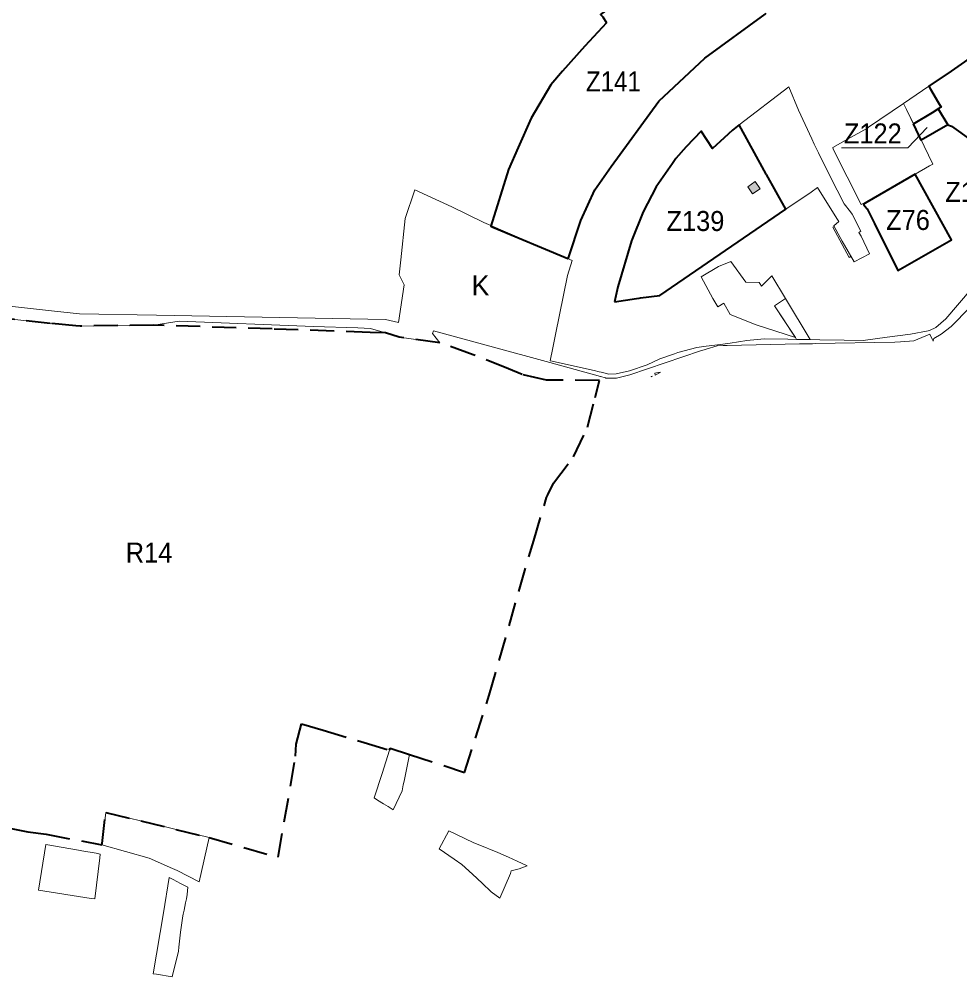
# Model space of a CAD drawing. Extents: x -650276 to -642489, y -1074425 to -1066658.
# Drawn here: x -647851 to -646722, y -1073778 to -1072629 of the extents above; entities that cross this region are included whole.
import ezdxf

# ---------------------------------------------------------------- set-up
doc = ezdxf.new("R2010")
doc.units = 0
doc.header["$LTSCALE"] = 9.6
doc.linetypes.add('MEDIUM_DASHED', pattern=[4.5, 3, -1.5])
for name, color, linetype, lineweight in [('1', 7, 'Continuous', 13), ('4', 7, 'Continuous', 40), ('43', 7, 'Continuous', 13), ('45', 7, 'Continuous', 40), ('46', 7, 'Continuous', 13), ('47', 7, 'Continuous', 13), ('61', 7, 'MEDIUM_DASHED', 40), ('62', 7, 'Continuous', 35)]:
    doc.layers.add(name, color=color, linetype=linetype, lineweight=lineweight)

msp = doc.modelspace()

# ---------------------------------------------------------------- hatches: boundary and pattern name
at = {"layer": '1'}
msp.add_hatch(color=256, dxfattribs=at).paths.add_polyline_path([(-646971.04, -1072838.99), (-646961.93, -1072832.83), (-646967.71, -1072824.33), (-646976.8, -1072830.5)])

# ---------------------------------------------------------------- linework, layer by layer
for p, q in [((-646855.3, -1072915.24), (-646853.054, -1072914.012)), ((-646920.755, -1073009.568), (-646919.54, -1073011.41)), ((-647087.96, -1073056.29), (-647081.63, -1073053.13)), ((-647092.58, -1073058.59), (-647090.83, -1073057.72)), ((-647424.76, -1073563.32), (-647420.98, -1073566.16))]:
    msp.add_line(p, q, dxfattribs=at)
for points in [[(-646849.28, -1072920.67), (-646830.67, -1072911.13), (-646840.69, -1072889.58), (-646843.77, -1072885.18), (-646841.08, -1072883.58), (-646851.49, -1072863.39), (-646853.76, -1072860.47), (-646861.08, -1072851.02), (-646877.79, -1072818.08), (-646892.15, -1072789.78), (-646897.03, -1072779.37), (-646900.09, -1072772.84), (-646916.01, -1072738.71), (-646927.67, -1072710.45), (-646987.154, -1072756.377), (-646954.51, -1072815.63)], [(-646778.198, -1072755.189), (-646755.1, -1072741.28), (-646744.94, -1072734.88), (-646747.87, -1072729.85), (-646757.5, -1072713.3), (-646759.55, -1072709.919), (-646789.83, -1072730.68)], [(-646789.83, -1072730.68), (-646786.56, -1072737.88), (-646778.198, -1072755.189)], [(-646954.51, -1072815.63), (-646931.1, -1072857.55), (-646900.9, -1072836.91), (-646893, -1072831.51), (-646869.88, -1072868.45), (-646867.436, -1072872.174), (-646873.71, -1072877.54), (-646863.45, -1072895.67), (-646849.28, -1072920.67)], [(-646873.3, -1072878.27), (-646874.85, -1072879.05), (-646855.3, -1072915.24)], [(-646853.054, -1072914.012), (-646863.45, -1072895.67), (-646873.298, -1072878.269)], [(-646997.71, -1072983.89), (-646966.57, -1072996.25), (-646919.54, -1073011.41), (-646944.76, -1072973.16), (-646931.62, -1072964.64), (-646947.88, -1072937.51), (-646960.29, -1072949.77), (-646962.41, -1072946.46), (-646963.13, -1072945.34), (-646979.1, -1072945.1), (-646997.15, -1072920.28), (-647011.86, -1072926.17), (-647032.61, -1072938.39), (-647018.82, -1072964.39)], [(-647018.82, -1072964.39), (-647012.79, -1072974.53), (-647005.6, -1072970.29), (-646997.71, -1072983.89)], [(-646931.62, -1072964.64), (-646944.76, -1072973.16), (-646920.755, -1073009.568)], [(-646919.54, -1073011.41), (-646918.156, -1073013.511), (-646902.136, -1073013.834), (-646931.62, -1072964.64)], [(-647081.63, -1073053.13), (-647081.66, -1073052.93), (-647088.34, -1073053.92), (-647087.96, -1073056.29)], [(-647090.83, -1073057.72), (-647092.67, -1073058), (-647092.58, -1073058.59)], [(-647420.98, -1073566.16), (-647413.53, -1073570.45), (-647407.81, -1073573.75), (-647401.88, -1073577.81), (-647391.32, -1073555.19), (-647389.85, -1073547.9), (-647388.91, -1073543.24), (-647382.45, -1073511.28), (-647405.5, -1073503.75), (-647406.33, -1073506.42), (-647415.01, -1073534.27), (-647424.76, -1073563.32)], [(-647661.19, -1073650.75), (-647634.63, -1073664.23), (-647622.63, -1073611.03), (-647686.73, -1073595.49), (-647746.63, -1073580.97), (-647751.31, -1073619.66), (-647694.7, -1073635.83)], [(-647250.75, -1073648.68), (-647241.27, -1073644.97), (-647253.11, -1073639.5), (-647263.52, -1073634.7), (-647276.6, -1073628.9), (-647300.1, -1073619.24), (-647303.33, -1073618.39), (-647306.03, -1073617.09), (-647335.29, -1073602.93), (-647346.74, -1073624.52), (-647328.83, -1073636.9), (-647319.58, -1073643.3)], [(-647753.78, -1073635.28), (-647753.27, -1073631.18), (-647758.16, -1073629.74), (-647775.27, -1073626.98), (-647779.3, -1073626.21), (-647818.46, -1073619.22), (-647827.23, -1073674.17)], [(-647827.23, -1073674.17), (-647764.01, -1073684.03), (-647759.96, -1073684.66), (-647753.78, -1073635.28)], [(-647694.7, -1073635.83), (-647666.8, -1073648.24), (-647661.19, -1073650.75)], [(-647319.58, -1073643.3), (-647306.74, -1073655.12), (-647295.17, -1073665.69), (-647284.57, -1073676.21), (-647274.16, -1073683.6), (-647261.22, -1073654.35), (-647260.32, -1073650.85), (-647250.75, -1073648.68)], [(-647670.44, -1073659.02), (-647677.6, -1073701.18), (-647689.67, -1073774.49)], [(-647648.15, -1073670.69), (-647652.31, -1073668.51), (-647656.92, -1073666.1), (-647665.93, -1073661.38), (-647670.44, -1073659.02)], [(-647689.67, -1073774.49), (-647685.72, -1073775.12), (-647666.96, -1073778.14), (-647659.58, -1073747.37), (-647659.07, -1073742.58), (-647657.12, -1073724.42), (-647654.08, -1073705.05), (-647653.73, -1073703.07), (-647652.75, -1073698.15), (-647650.96, -1073689.17), (-647650.01, -1073684.42), (-647649.01, -1073679.36), (-647648.15, -1073670.69)]]:
    msp.add_lwpolyline(points, dxfattribs=at)
for points in [[(-646857.61, -1072818.4), (-646840.87, -1072851.94), (-646838.22, -1072850.53), (-646837.81, -1072851.3), (-646775.85, -1072815.39), (-646758.9, -1072805.56), (-646754.96, -1072803.29), (-646786.56, -1072737.88), (-646789.83, -1072730.68), (-646831.91, -1072759.13), (-646833.27, -1072760.04), (-646857.03, -1072773.34), (-646874.79, -1072783.28), (-646874.23, -1072785.2)], [(-646971.04, -1072838.99), (-646961.93, -1072832.83), (-646967.71, -1072824.33), (-646976.8, -1072830.5)]]:
    msp.add_lwpolyline(points, close=True, dxfattribs=at)
at = {"layer": '4'}
for points in [[(-646987.154, -1072756.377), (-646995.02, -1072762.45), (-647005.249, -1072771.938), (-647019.06, -1072784.57), (-647032.7, -1072763.68), (-647050.492, -1072782.771)], [(-646954.7, -1072815.232), (-646957.105, -1072810.92), (-646987.154, -1072756.377)], [(-647050.492, -1072782.771), (-647063.04, -1072796.74), (-647067.22, -1072802.77), (-647086.65, -1072830.76), (-647102.38, -1072860.7), (-647116.33, -1072895.3)], [(-647136.39, -1072968.63), (-647110.32, -1072964.56), (-647107.01, -1072964.04), (-647105.4, -1072963.84), (-647082.36, -1072960.95), (-646931.1, -1072857.55), (-646954.51, -1072815.63), (-646954.7, -1072815.232)], [(-647116.33, -1072895.3), (-647132.47, -1072950.4), (-647136.39, -1072968.63)]]:
    msp.add_lwpolyline(points, dxfattribs=at)
at = {"layer": '45'}
for points in [[(-646993.05, -1072505.68), (-646994.2, -1072506.52), (-647153.2, -1072623.68), (-647150.75, -1072626.84), (-647146.21, -1072634.02)], [(-647192.069, -1072916.856), (-647177.144, -1072871.095), (-647160.08, -1072833.974), (-647140.764, -1072806.081), (-647083.498, -1072727.769), (-647028.234, -1072676.101), (-646956.061, -1072623.348), (-646954.617, -1072622.388)], [(-647146.21, -1072634.02), (-647172.36, -1072661.69), (-647198.77, -1072691.71), (-647212.92, -1072708.05)], [(-646737.05, -1072756.4), (-646732.5, -1072757.63), (-646708.65, -1072775.02), (-646702.45, -1072773.39), (-646712.46, -1072766.76), (-646711.79, -1072750.02), (-646677.39, -1072724.85), (-646660.89, -1072709.97), (-646643.36, -1072746.04), (-646647.93, -1072759.01), (-646612.11, -1072774.56), (-646581.92, -1072723.91), (-646589.37, -1072709.83), (-646605.23, -1072679.37), (-646627.32, -1072636.95), (-646629.86, -1072632.07), (-646648.27, -1072647.48), (-646669.6, -1072654.53), (-646697.89, -1072667.65)], [(-646697.89, -1072667.65), (-646732.95, -1072691.68), (-646759.491, -1072709.878), (-646757.5, -1072713.3), (-646747.87, -1072729.85), (-646744.94, -1072734.88), (-646748.3, -1072737.01), (-646737.05, -1072756.4)], [(-647212.92, -1072708.05), (-647236.54, -1072748.09), (-647252.29, -1072783.24), (-647263.58, -1072809.97), (-647284.75, -1072877.79), (-647282.31, -1072878.82), (-647192.718, -1072916.582), (-647192.069, -1072916.856)]]:
    msp.add_lwpolyline(points, dxfattribs=at)
for points in [[(-646778.2, -1072755.19), (-646755.1, -1072741.28), (-646748.3, -1072737.01), (-646737.05, -1072756.4), (-646768.74, -1072774.78)], [(-646837.81, -1072851.3), (-646836.5, -1072853.76), (-646833.67, -1072857.15), (-646824.89, -1072874.66), (-646796.68, -1072930.92), (-646732.28, -1072894.29), (-646775.85, -1072815.39), (-646834.08, -1072849.15)], [(-646837.81, -1072851.3), (-646836.5, -1072853.76), (-646833.67, -1072857.15), (-646824.89, -1072874.66), (-646796.68, -1072930.92), (-646732.28, -1072894.29), (-646775.85, -1072815.39), (-646834.08, -1072849.15)]]:
    msp.add_lwpolyline(points, close=True, dxfattribs=at)
at = {"layer": '46'}
msp.add_lwpolyline([(-646864.278, -1072783.783), (-646784.878, -1072783.783), (-646761.687, -1072759.411)], dxfattribs=at)
at = {"layer": '47'}
for points in [[(-646692.432, -1072934.135), (-646739.241, -1072988.798), (-646751.061, -1072999.106), (-646758.883, -1073002.885), (-646760.416, -1073003.25), (-646781.703, -1073007.452), (-646809.778, -1073011.019), (-646838.25, -1073014.938), (-646861.07, -1073014.672), (-646890.523, -1073014.073), (-646904.131, -1073013.793), (-646914.796, -1073013.573), (-646918.156, -1073013.511), (-646928.807, -1073013.313), (-646956.919, -1073012.775), (-646978.077, -1073014.931), (-646997.824, -1073018.092), (-647006.715, -1073019.236), (-647009.402, -1073019.582), (-647026.763, -1073021.811), (-647037.971, -1073023.24), (-647060.677, -1073029.351), (-647064.784, -1073030.747), (-647082.267, -1073036.684), (-647097.466, -1073044.268), (-647118.513, -1073051.327), (-647134.596, -1073054.974), (-647143.312, -1073055.421), (-647147.85, -1073054.204), (-647152.621, -1073052.925), (-647154.999, -1073052.287), (-647161.068, -1073050.946), (-647161.068, -1073050.946), (-647161.068, -1073050.946), (-647213.218, -1073039.42), (-647213.562, -1073039.322), (-647210.396, -1073023.593), (-647207.176, -1073007.598), (-647192.93, -1072936.82), (-647187.445, -1072918.804), (-647293.317, -1072873.549), (-647293.351, -1072873.533), (-647331.82, -1072854.49), (-647375.92, -1072833.99), (-647387.64, -1072868.69), (-647392.96, -1072918.277), (-647394.87, -1072936.08), (-647388.62, -1072948.03), (-647395.47, -1072993.25), (-647411.293, -1072989.813), (-647411.294, -1072989.813), (-647411.294, -1072989.813), (-647411.298, -1072989.813), (-647685.748, -1072984.544), (-647778.296, -1072982.767), (-647811.752, -1072979.4), (-648023.495, -1072955.875)], [(-648022.279, -1072971.102), (-647813.331, -1072994.317), (-647782.72, -1072997.397), (-647777.337, -1072997.711), (-647689.11, -1072996.49), (-647658.437, -1072991.865), (-647658.437, -1072991.865), (-647658.437, -1072991.865), (-647658.437, -1072991.865), (-647658.437, -1072991.865), (-647658.437, -1072991.865), (-647497.35, -1072997.93), (-647444.42, -1072999.87), (-647429.276, -1073000.424), (-647411.34, -1073005.89), (-647394.782, -1073011.002), (-647346.22, -1073017.52), (-647354.76, -1073006.65), (-647353.78, -1073003.1), (-647213.99, -1073041.449), (-647153.44, -1073058.06), (-647152.96, -1073058.19), (-647147.91, -1073059.64), (-647147.43, -1073059.78), (-647147.17, -1073059.97), (-647134.03, -1073059.94), (-647118.27, -1073055.88), (-647033.44, -1073027.43), (-647028.91, -1073025.91), (-647026.54, -1073025.11), (-647013.4, -1073021.42), (-647006.15, -1073020.99), (-647001.66, -1073020.72), (-646914.54, -1073019), (-646913.94, -1073018.99), (-646899.22, -1073018.7), (-646895.76, -1073018.63), (-646800.44, -1073016.74), (-646793.8, -1073016.61), (-646777.74, -1073015.29), (-646758.545, -1073007.234), (-646755.58, -1073013.43), (-646754.581, -1073015.554)], [(-646754.581, -1073015.554), (-646753.573, -1073012.306), (-646744.92, -1073007.46), (-646732.95, -1072998.07), (-646710.3, -1072975.31)]]:
    msp.add_lwpolyline(points, dxfattribs=at)
at = {"layer": '61'}
msp.add_lwpolyline([(-647861.92, -1073599.87), (-647840.12, -1073604.27), (-647818.3, -1073607.2), (-647751.31, -1073619.66), (-647751.124, -1073618.122), (-647746.63, -1073580.97), (-647622.63, -1073611.03), (-647539.83, -1073634.79), (-647519.11, -1073513.63), (-647518.27, -1073499.08), (-647511.932, -1073474.5), (-647486.04, -1073482.326), (-647436.7, -1073497.24), (-647406.33, -1073506.42), (-647405.5, -1073503.75), (-647382.45, -1073511.28), (-647316.269, -1073532.9), (-647287.03, -1073440.3), (-647233.5, -1073254.63), (-647218, -1073203.36), (-647216.34, -1073199.89), (-647209.63, -1073185.84), (-647185.73, -1073154.33), (-647168.83, -1073118.8), (-647159.72, -1073083.31), (-647154.77, -1073062.68), (-647218.06, -1073062.37), (-647247.46, -1073055.63), (-647263.8, -1073049), (-647305.94, -1073031.89), (-647346.22, -1073017.52), (-647394.782, -1073011.002), (-647411.34, -1073005.89), (-647429.65, -1073005.19), (-647547.02, -1073001.04), (-647689.11, -1072996.49), (-647777.336, -1072997.711), (-647782.72, -1072997.397), (-647813.331, -1072994.317), (-648022.279, -1072971.102)], dxfattribs=at)

# ---------------------------------------------------------------- texts
at = {"layer": '4', "width": 0.95}
msp.add_text('Z139', height=24, dxfattribs=at).set_placement((-647074.31, -1072883.554))
at = {"layer": '43'}
msp.add_text('K', height=24, dxfattribs=at).set_placement((-647307.985, -1072960.845))
msp.add_text('K', height=24, dxfattribs=at).set_placement((-647307.985, -1072960.845))
at = {"layer": '46'}
for s, width, p in [('Z141', 0.9, (-647170.833, -1072716.129)), ('Z122', 0.95, (-646861.605, -1072778.534)), ('Z126', 0.95, (-646740.041, -1072848.718)), ('Z76', 0.95, (-646810.899, -1072882.315)), ('Z76', 0.95, (-646810.899, -1072882.315))]:
    msp.add_text(s, height=24, dxfattribs=dict(at, width=width)).set_placement(p)
at = {"layer": '62', "width": 0.95}
msp.add_text('R14', height=24, dxfattribs=at).set_placement((-647722.71, -1073281.294))

doc.saveas('drawing.dxf')
